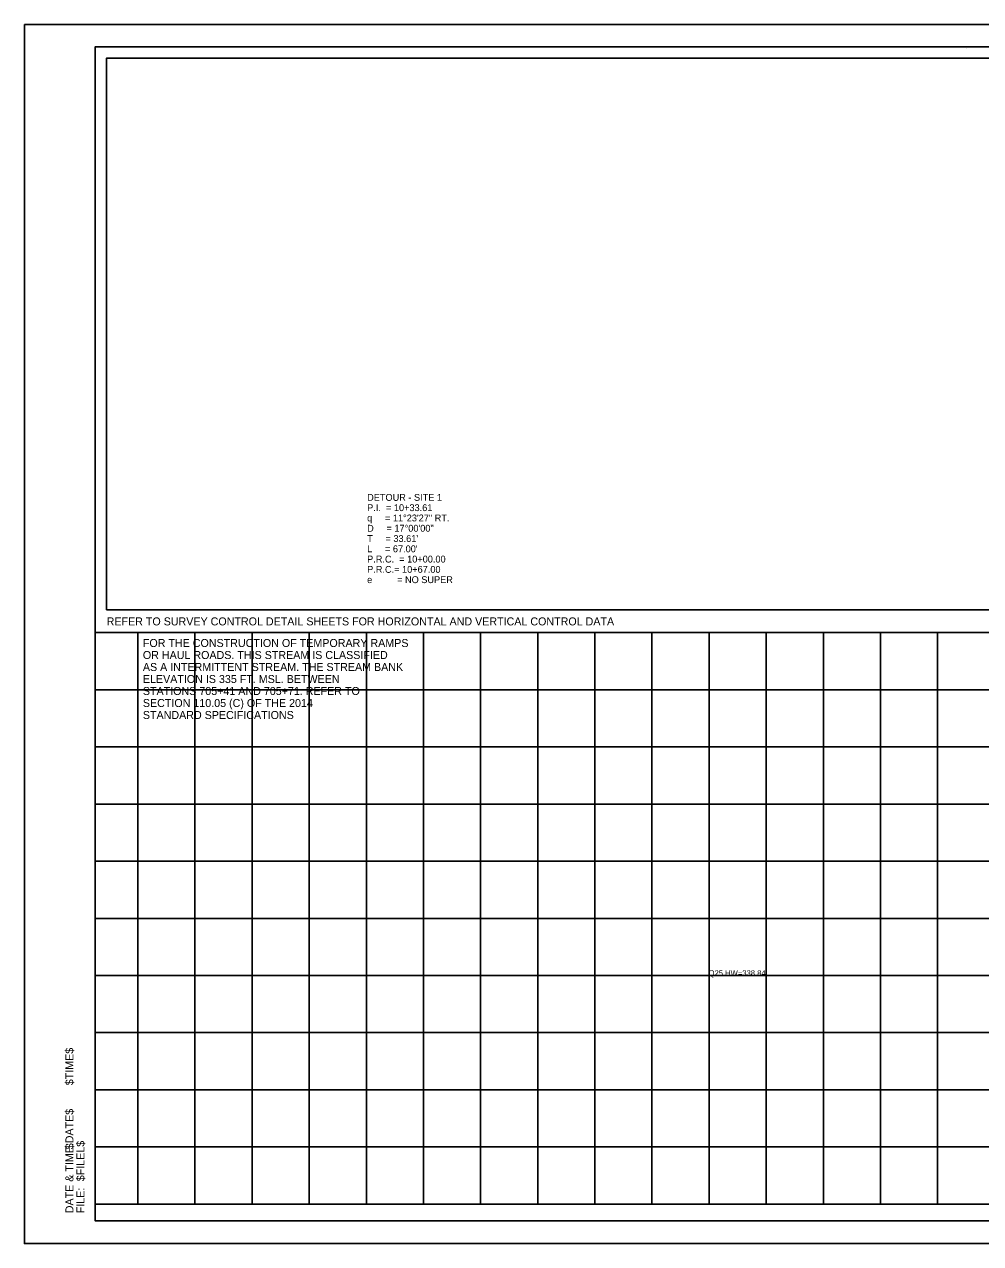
# Model space of a CAD drawing. Extents: x 816090 to 819714, y 1801340 to 1803641.
# Drawn here: x 818048 to 818885, y 1802574 to 1803641 of the extents above; entities that cross this region are included whole.
import ezdxf

# ---------------------------------------------------------------- set-up
doc = ezdxf.new("R2010")
doc.units = 0
for name, color, linetype in [('R_Border', 7, 'Continuous'), ('R_Border Notes', 7, 'Continuous'), ('R_BORDER SURVEY NOTE', 7, 'Continuous'), ('R_Detour Curve Annot', 7, 'Continuous'), ('R_No Plot', 7, 'Continuous'), ('R_RC Box Annot', 7, 'Continuous')]:
    doc.layers.add(name, color=color, linetype=linetype)

msp = doc.modelspace()

# ---------------------------------------------------------------- linework, layer by layer
at = {"layer": 'R_Border'}
for p, q in [((818109.6, 1803621.1), (819690.5, 1803621.1)), ((818109.6, 1802593.8), (818109.6, 1803621.1)), ((818872.2, 1803619.8), (818872.2, 1803619.8)), ((818872.2, 1803619.8), (818872.2, 1803619.8)), ((819690.5, 1803108.5), (818109.6, 1803108.5)), ((818146.9, 1802608.5), (818146.9, 1803108.5)), ((818196.9, 1802608.5), (818196.9, 1803108.5)), ((818246.9, 1802608.5), (818246.9, 1803108.5)), ((818296.9, 1802608.5), (818296.9, 1803108.5)), ((818346.9, 1802608.5), (818346.9, 1803108.5)), ((818396.9, 1802608.5), (818396.9, 1803108.5)), ((818446.9, 1802608.5), (818446.9, 1803108.5)), ((818496.9, 1802608.5), (818496.9, 1803108.5)), ((818546.9, 1802608.5), (818546.9, 1803108.5)), ((818596.9, 1802608.5), (818596.9, 1803108.5)), ((818646.9, 1802608.5), (818646.9, 1803108.5)), ((818696.9, 1802608.5), (818696.9, 1803108.5)), ((818746.9, 1802608.5), (818746.9, 1803108.5)), ((818796.9, 1802608.5), (818796.9, 1803108.5)), ((818846.9, 1802608.5), (818846.9, 1803108.5)), ((819690.5, 1803058.5), (818109.6, 1803058.5)), ((819690.5, 1803008.5), (818109.6, 1803008.5)), ((819690.5, 1802958.5), (818109.6, 1802958.5)), ((819690.5, 1802908.5), (818109.6, 1802908.5)), ((819690.5, 1802858.5), (818109.6, 1802858.5)), ((819690.5, 1802808.5), (818109.6, 1802808.5)), ((819690.5, 1802758.5), (818109.6, 1802758.5)), ((819690.5, 1802708.5), (818109.6, 1802708.5)), ((819690.5, 1802658.5), (818109.6, 1802658.5)), ((819690.5, 1802608.5), (818109.6, 1802608.5)), ((818109.6, 1802593.8), (818109.6, 1802593.8)), ((819690.5, 1802593.8), (818109.6, 1802593.8))]:
    msp.add_line(p, q, dxfattribs=at)
at = {"layer": 'R_No Plot'}
for p, q in [((818047.6, 1803640.6), (819714.3, 1803640.6)), ((818047.6, 1802573.9), (819714.3, 1802573.9))]:
    msp.add_line(p, q, dxfattribs=at)
for points in [[(818047.6, 1803640.6), (819714.3, 1803640.6), (819714.3, 1802573.9), (818047.6, 1802573.9)], [(819377.3, 1803621.1), (819377.3, 1803571.7), (819457.8, 1803571.7), (819576.4, 1803571.7), (819576.4, 1803461.7), (819690.5, 1803461.7), (819690.5, 1803108.5), (818109.6, 1803108.5), (818109.6, 1803621.1)], [(819680.5, 1803128.5), (818119.6, 1803128.5), (818119.6, 1803611.1), (819367.3, 1803611.1), (819367.3, 1803561.7), (819576.4, 1803561.7), (819576.4, 1803461.7), (819680.5, 1803461.7)], [(819680.5, 1803128.5), (818119.6, 1803128.5), (818119.6, 1803611.1), (819367.3, 1803611.1), (819367.3, 1803561.7), (819576.4, 1803561.7), (819576.4, 1803461.7), (819680.5, 1803461.7)], [(819680.5, 1803128.5), (818119.6, 1803128.5), (818119.6, 1803611.1), (819367.3, 1803611.1), (819367.3, 1803561.7), (819576.4, 1803561.7), (819576.4, 1803461.7), (819680.5, 1803461.7)], [(818109.6, 1803108.5), (819690.5, 1803108.5), (819690.5, 1802593.8), (818109.6, 1802593.8)], [(818109.6, 1803108.5), (819690.5, 1803108.5), (819690.5, 1802593.8), (818109.6, 1802593.8)]]:
    msp.add_lwpolyline(points, close=True, dxfattribs=at)

# ---------------------------------------------------------------- texts
at = {"layer": 'R_Border Notes'}
for s, p in [('$TIME$', (818090.5, 1802712.5)), ('$DATE$', (818090.5, 1802656.5)), ('DATE & TIME:', (818090.5, 1802600.5)), ('$FILEL$', (818100.2, 1802628.5)), ('FILE: ', (818100.2, 1802600.5))]:
    msp.add_text(s, height=7, rotation=90, dxfattribs=at).set_placement(p)
at = {"layer": 'R_BORDER SURVEY NOTE'}
for s, p in [('REFER TO SURVEY CONTROL DETAIL SHEETS FOR HORIZONTAL AND VERTICAL CONTROL DATA', (818119.6, 1803114.8)), ('FOR THE CONSTRUCTION OF TEMPORARY RAMPS', (818151.3, 1803095.9)), ('OR HAUL ROADS. THIS STREAM IS CLASSIFIED', (818151.3, 1803085.4)), ('AS A INTERMITTENT STREAM. THE STREAM BANK', (818151.3, 1803074.9)), ('ELEVATION IS 335 FT. MSL. BETWEEN ', (818151.3, 1803064.4)), ('STATIONS 705+41 AND 705+71. REFER TO', (818151.3, 1803053.9)), ('SECTION 110.05 (C) OF THE 2014 ', (818151.3, 1803043.4)), ('STANDARD SPECIFICATIONS', (818151.3, 1803032.9))]:
    msp.add_text(s, height=7, dxfattribs=at).set_placement(p)
at = {"layer": 'R_Detour Curve Annot'}
for s, p in [('DETOUR - SITE 1', (818347.6, 1803223.8)), ('P.I.  = 10+33.61', (818347.6, 1803214.8)), ('q     = 11%%d23\'27" RT.', (818347.6, 1803205.8)), ("T     = 33.61'", (818347.6, 1803187.8)), ('D     = 17%%d00\'00"', (818347.6, 1803196.8)), ("L     = 67.00'", (818347.6, 1803178.8)), ('P.R.C.  = 10+00.00', (818347.6, 1803169.8)), ('P.R.C.= 10+67.00', (818347.6, 1803160.8)), ('e', (818347.6, 1803151.8)), (' = NO SUPER', (818371.6, 1803151.8))]:
    msp.add_text(s, height=6, dxfattribs=at).set_placement(p)
at = {"layer": 'R_RC Box Annot'}
msp.add_text('Q25 HW=338.84', height=5, dxfattribs=at).set_placement((818646.4, 1802808.1))

doc.saveas('drawing.dxf')
